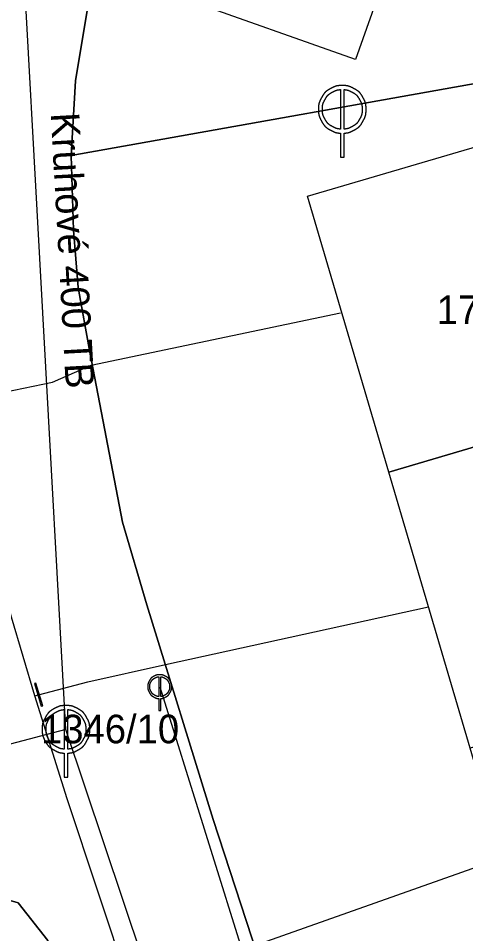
# Model space of a CAD drawing. Extents: x -562248 to -562040, y -1079385 to -1079027.
# Drawn here: x -562125.69 to -562102.21, y -1079149.79 to -1079101.77 of the extents above; entities that cross this region are included whole.
import ezdxf

# ---------------------------------------------------------------- set-up
doc = ezdxf.new("R2010")
doc.units = 0
for name, color, linetype in [('Armatura vodovodní', 7, 'Continuous'), ('Default', 7, 'Continuous'), ('Kanalizační stoka', 7, 'Continuous'), ('Kanalizační šachta', 7, 'Continuous'), ('Parcela-polygon', 7, 'Continuous'), ('Parcela-text', 7, 'Continuous'), ('Popis kmenové stoky', 7, 'Continuous'), ('Vodovodní přípojka', 7, 'Continuous'), ('Vodovodní řad', 7, 'Continuous')]:
    doc.layers.add(name, color=color, linetype=linetype)

msp = doc.modelspace()

# ---------------------------------------------------------------- linework, layer by layer
at = {"layer": 'Armatura vodovodní'}
msp.add_lwpolyline([(-562124.488, -1079137.861), (-562124.413, -1079137.839), (-562124.774, -1079136.642), (-562124.849, -1079136.665)], close=True, dxfattribs=at)
at = {"layer": 'Default'}
for points in [[(-562109.303, -1079105.459), (-562109.502, -1079105.567), (-562109.657, -1079105.721), (-562109.769, -1079105.921)], [(-562108.688, -1079105.298), (-562108.899, -1079105.298), (-562109.105, -1079105.352), (-562109.303, -1079105.459)], [(-562108.074, -1079105.459), (-562108.273, -1079105.352), (-562108.478, -1079105.298), (-562108.688, -1079105.298)], [(-562107.606, -1079105.921), (-562107.719, -1079105.721), (-562107.874, -1079105.567), (-562108.074, -1079105.459)], [(-562109.769, -1079105.921), (-562109.882, -1079106.121), (-562109.938, -1079106.33), (-562109.938, -1079106.548)], [(-562109.591, -1079106.027), (-562109.498, -1079105.86), (-562109.369, -1079105.732), (-562109.203, -1079105.642)], [(-562109.203, -1079105.642), (-562109.06, -1079105.566), (-562108.922, -1079105.522), (-562108.79, -1079105.511)], [(-562108.585, -1079105.511), (-562108.453, -1079105.522), (-562108.317, -1079105.566), (-562108.175, -1079105.642)], [(-562108.175, -1079105.642), (-562108.009, -1079105.732), (-562107.879, -1079105.86), (-562107.786, -1079106.027)], [(-562107.438, -1079106.548), (-562107.438, -1079106.33), (-562107.494, -1079106.121), (-562107.606, -1079105.921)], [(-562109.73, -1079106.548), (-562109.73, -1079106.368), (-562109.684, -1079106.194), (-562109.591, -1079106.027)], [(-562107.786, -1079106.027), (-562107.692, -1079106.194), (-562107.645, -1079106.368), (-562107.645, -1079106.548)], [(-562109.938, -1079106.548), (-562109.938, -1079106.765), (-562109.883, -1079106.972), (-562109.773, -1079107.171)], [(-562109.594, -1079107.066), (-562109.685, -1079106.901), (-562109.73, -1079106.729), (-562109.73, -1079106.548)], [(-562107.645, -1079106.548), (-562107.645, -1079106.729), (-562107.691, -1079106.901), (-562107.782, -1079107.066)], [(-562107.603, -1079107.171), (-562107.493, -1079106.972), (-562107.438, -1079106.765), (-562107.438, -1079106.548)], [(-562109.773, -1079107.171), (-562109.663, -1079107.369), (-562109.509, -1079107.523), (-562109.31, -1079107.632)], [(-562109.208, -1079107.449), (-562109.374, -1079107.358), (-562109.502, -1079107.23), (-562109.594, -1079107.066)], [(-562107.782, -1079107.066), (-562107.873, -1079107.23), (-562108.001, -1079107.358), (-562108.165, -1079107.449)], [(-562108.065, -1079107.632), (-562107.867, -1079107.523), (-562107.712, -1079107.369), (-562107.603, -1079107.171)], [(-562109.31, -1079107.632), (-562109.136, -1079107.73), (-562108.963, -1079107.784), (-562108.79, -1079107.796)], [(-562108.79, -1079107.583), (-562108.927, -1079107.574), (-562109.066, -1079107.529), (-562109.208, -1079107.449)], [(-562108.165, -1079107.449), (-562108.309, -1079107.529), (-562108.449, -1079107.574), (-562108.585, -1079107.583)], [(-562108.585, -1079107.796), (-562108.413, -1079107.784), (-562108.239, -1079107.73), (-562108.065, -1079107.632)], [(-562118.27, -1079136.205), (-562118.376, -1079136.205), (-562118.478, -1079136.232), (-562118.578, -1079136.286)], [(-562117.962, -1079136.286), (-562118.062, -1079136.232), (-562118.164, -1079136.205), (-562118.27, -1079136.205)], [(-562118.811, -1079136.516), (-562118.867, -1079136.616), (-562118.895, -1079136.721), (-562118.895, -1079136.83)], [(-562118.578, -1079136.286), (-562118.677, -1079136.339), (-562118.755, -1079136.416), (-562118.811, -1079136.516)], [(-562118.79, -1079136.83), (-562118.79, -1079136.739), (-562118.767, -1079136.652), (-562118.72, -1079136.569)], [(-562118.72, -1079136.569), (-562118.674, -1079136.486), (-562118.609, -1079136.421), (-562118.526, -1079136.376)], [(-562118.526, -1079136.376), (-562118.455, -1079136.338), (-562118.386, -1079136.316), (-562118.321, -1079136.31)], [(-562118.219, -1079136.31), (-562118.152, -1079136.316), (-562118.084, -1079136.338), (-562118.014, -1079136.376)], [(-562118.014, -1079136.376), (-562117.931, -1079136.421), (-562117.866, -1079136.486), (-562117.818, -1079136.569)], [(-562117.729, -1079136.516), (-562117.785, -1079136.416), (-562117.863, -1079136.339), (-562117.962, -1079136.286)], [(-562117.818, -1079136.569), (-562117.771, -1079136.652), (-562117.748, -1079136.739), (-562117.748, -1079136.83)], [(-562117.645, -1079136.83), (-562117.645, -1079136.721), (-562117.673, -1079136.616), (-562117.729, -1079136.516)], [(-562118.895, -1079136.83), (-562118.895, -1079136.937), (-562118.867, -1079137.041), (-562118.812, -1079137.14)], [(-562118.812, -1079137.14), (-562118.757, -1079137.239), (-562118.679, -1079137.317), (-562118.58, -1079137.372)], [(-562118.722, -1079137.088), (-562118.767, -1079137.005), (-562118.79, -1079136.92), (-562118.79, -1079136.83)], [(-562118.529, -1079137.279), (-562118.612, -1079137.234), (-562118.676, -1079137.17), (-562118.722, -1079137.088)], [(-562117.816, -1079137.088), (-562117.861, -1079137.17), (-562117.926, -1079137.234), (-562118.009, -1079137.279)], [(-562117.958, -1079137.372), (-562117.858, -1079137.317), (-562117.781, -1079137.239), (-562117.727, -1079137.14)], [(-562117.748, -1079136.83), (-562117.748, -1079136.92), (-562117.77, -1079137.005), (-562117.816, -1079137.088)], [(-562117.727, -1079137.14), (-562117.672, -1079137.041), (-562117.645, -1079136.937), (-562117.645, -1079136.83)], [(-562118.58, -1079137.372), (-562118.494, -1079137.421), (-562118.408, -1079137.448), (-562118.321, -1079137.453)], [(-562118.321, -1079137.348), (-562118.39, -1079137.343), (-562118.459, -1079137.32), (-562118.529, -1079137.279)], [(-562118.009, -1079137.279), (-562118.08, -1079137.32), (-562118.15, -1079137.343), (-562118.219, -1079137.348)], [(-562118.219, -1079137.453), (-562118.132, -1079137.448), (-562118.045, -1079137.421), (-562117.958, -1079137.372)], [(-562123.805, -1079137.981), (-562124.004, -1079138.089), (-562124.159, -1079138.242), (-562124.272, -1079138.443)], [(-562123.19, -1079137.82), (-562123.402, -1079137.82), (-562123.607, -1079137.874), (-562123.805, -1079137.981)], [(-562123.705, -1079138.164), (-562123.562, -1079138.088), (-562123.424, -1079138.044), (-562123.293, -1079138.032)], [(-562122.576, -1079137.981), (-562122.775, -1079137.874), (-562122.98, -1079137.82), (-562123.19, -1079137.82)], [(-562123.087, -1079138.032), (-562122.956, -1079138.044), (-562122.819, -1079138.088), (-562122.677, -1079138.164)], [(-562122.108, -1079138.443), (-562122.221, -1079138.242), (-562122.377, -1079138.089), (-562122.576, -1079137.981)], [(-562124.272, -1079138.443), (-562124.384, -1079138.643), (-562124.44, -1079138.852), (-562124.44, -1079139.07)], [(-562124.232, -1079139.07), (-562124.232, -1079138.889), (-562124.186, -1079138.716), (-562124.093, -1079138.549)], [(-562124.093, -1079138.549), (-562124.001, -1079138.382), (-562123.871, -1079138.254), (-562123.705, -1079138.164)], [(-562122.677, -1079138.164), (-562122.511, -1079138.254), (-562122.381, -1079138.382), (-562122.288, -1079138.549)], [(-562122.288, -1079138.549), (-562122.194, -1079138.716), (-562122.148, -1079138.889), (-562122.148, -1079139.07)], [(-562121.94, -1079139.07), (-562121.94, -1079138.852), (-562121.996, -1079138.643), (-562122.108, -1079138.443)], [(-562124.44, -1079139.07), (-562124.44, -1079139.286), (-562124.385, -1079139.494), (-562124.275, -1079139.693)], [(-562124.096, -1079139.588), (-562124.187, -1079139.423), (-562124.232, -1079139.251), (-562124.232, -1079139.07)], [(-562122.148, -1079139.07), (-562122.148, -1079139.251), (-562122.193, -1079139.423), (-562122.284, -1079139.588)], [(-562122.105, -1079139.693), (-562121.995, -1079139.494), (-562121.94, -1079139.286), (-562121.94, -1079139.07)], [(-562123.71, -1079139.971), (-562123.876, -1079139.88), (-562124.005, -1079139.752), (-562124.096, -1079139.588)], [(-562122.284, -1079139.588), (-562122.375, -1079139.752), (-562122.503, -1079139.88), (-562122.668, -1079139.971)], [(-562124.275, -1079139.693), (-562124.165, -1079139.891), (-562124.011, -1079140.045), (-562123.813, -1079140.154)], [(-562123.293, -1079140.105), (-562123.429, -1079140.095), (-562123.568, -1079140.051), (-562123.71, -1079139.971)], [(-562122.668, -1079139.971), (-562122.811, -1079140.051), (-562122.951, -1079140.095), (-562123.087, -1079140.105)], [(-562122.567, -1079140.154), (-562122.369, -1079140.045), (-562122.215, -1079139.891), (-562122.105, -1079139.693)], [(-562123.813, -1079140.154), (-562123.638, -1079140.252), (-562123.465, -1079140.306), (-562123.293, -1079140.318)], [(-562123.087, -1079140.318), (-562122.915, -1079140.306), (-562122.742, -1079140.252), (-562122.567, -1079140.154)]]:
    msp.add_open_spline(points, degree=2, dxfattribs=at)
at = {"layer": 'Kanalizační stoka'}
for points in [[(-562123.19, -1079139.07), (-562125.61, -1079095.35)], [(-562118.27, -1079136.83), (-562108.95, -1079166.63)], [(-562123.19, -1079139.07), (-562151.509, -1079146.524)], [(-562098.95, -1079211.35), (-562123.19, -1079139.07)]]:
    msp.add_lwpolyline(points, dxfattribs=at)
at = {"layer": 'Kanalizační šachta'}
for points in [[(-562108.79, -1079105.511), (-562108.79, -1079107.583)], [(-562108.585, -1079107.583), (-562108.585, -1079105.511)], [(-562108.79, -1079109.048), (-562108.585, -1079109.048), (-562108.585, -1079107.796)], [(-562108.79, -1079107.796), (-562108.79, -1079109.048)], [(-562118.321, -1079136.31), (-562118.321, -1079137.348)], [(-562118.219, -1079137.348), (-562118.219, -1079136.31)], [(-562118.321, -1079138.08), (-562118.219, -1079138.08), (-562118.219, -1079137.453)], [(-562118.321, -1079137.453), (-562118.321, -1079138.08)], [(-562123.293, -1079138.032), (-562123.293, -1079140.105)], [(-562123.087, -1079140.105), (-562123.087, -1079138.032)], [(-562123.293, -1079141.57), (-562123.087, -1079141.57), (-562123.087, -1079140.318)], [(-562123.293, -1079140.318), (-562123.293, -1079141.57)]]:
    msp.add_lwpolyline(points, dxfattribs=at)
at = {"layer": 'Parcela-polygon'}
for points in [[(-562089.427, -1079062.836), (-562106.84, -1079056.62), (-562119.65, -1079091.82), (-562121.03, -1079096.76), (-562122.05, -1079101.16), (-562122.69, -1079105.05), (-562122.92, -1079108.96), (-562097.98, -1079104.526)], [(-562117.01, -1079100.74), (-562111.46, -1079085.11), (-562105.93, -1079069.43), (-562096.89, -1079072.69), (-562102.44, -1079088.31), (-562107.99, -1079103.94), (-562117.01, -1079100.74)], [(-562074.7, -1079253.09), (-562081.96, -1079237.32), (-562088.81, -1079221.44), (-562094.66, -1079207.06), (-562098.96, -1079196.12), (-562103.67, -1079183.92), (-562101.64, -1079183.14), (-562108.26, -1079165.24), (-562109.03, -1079162.72), (-562110.57, -1079158.43), (-562113.13, -1079150.92), (-562115.47, -1079143.79), (-562118.94, -1079132.53), (-562120.22, -1079128.2), (-562121.94, -1079119.29), (-562122.55, -1079115.89), (-562122.79, -1079112.89), (-562122.92, -1079108.96), (-562122.69, -1079105.05), (-562122.05, -1079101.16)], [(-562097.98, -1079104.526), (-562122.92, -1079108.96), (-562122.79, -1079112.89), (-562122.55, -1079115.89), (-562121.94, -1079119.29), (-562120.22, -1079128.2), (-562118.94, -1079132.53), (-562115.47, -1079143.79), (-562113.13, -1079150.92), (-562110.57, -1079158.43), (-562109.03, -1079162.72), (-562081.378, -1079153.144)], [(-562101.27, -1079108.39), (-562097, -1079122.85), (-562092.73, -1079137.34), (-562088.46, -1079151.82), (-562097.7, -1079154.55), (-562101.98, -1079140.06), (-562106.25, -1079125.58), (-562110.52, -1079111.1), (-562101.27, -1079108.39)], [(-562130.204, -1079213.482), (-562129.52, -1079213.24), (-562126.56, -1079212.06), (-562110.18, -1079204.89), (-562109.412, -1079204.67), (-562108.694, -1079204.319), (-562108.049, -1079203.848), (-562107.496, -1079203.271), (-562107.054, -1079202.606), (-562106.734, -1079201.874), (-562106.547, -1079201.097), (-562106.5, -1079200.3), (-562107.01, -1079197.84), (-562112.9, -1079182.58), (-562117.83, -1079168.5), (-562124.14, -1079150.14), (-562125.7, -1079148.16), (-562127.71, -1079147.6), (-562130.14, -1079147.9), (-562151.942, -1079151.733)], [(-562151.942, -1079151.733), (-562130.14, -1079147.9), (-562127.71, -1079147.6), (-562125.7, -1079148.16), (-562124.14, -1079150.14), (-562117.83, -1079168.5), (-562112.9, -1079182.58), (-562107.01, -1079197.84), (-562106.5, -1079200.3), (-562100.28, -1079214.7), (-562095.19, -1079227.16), (-562092.25, -1079234.14), (-562087.93, -1079243.96)]]:
    msp.add_lwpolyline(points, dxfattribs=at)
for points in [[(-562111.46, -1079085.11), (-562102.44, -1079088.31), (-562107.99, -1079103.94), (-562117.01, -1079100.74)], [(-562110.52, -1079111.1), (-562101.27, -1079108.39), (-562097, -1079122.85), (-562106.25, -1079125.58)], [(-562097, -1079122.85), (-562092.73, -1079137.34), (-562101.98, -1079140.06), (-562106.25, -1079125.58)]]:
    msp.add_lwpolyline(points, close=True, dxfattribs=at)
at = {"layer": 'Vodovodní přípojka'}
for points in [[(-562128.484, -1079121.808), (-562123.89, -1079120.86), (-562121.868, -1079119.966), (-562108.775, -1079117.222)], [(-562124.818, -1079137.317), (-562124.633, -1079137.252), (-562122.045, -1079136.57), (-562117.961, -1079135.673), (-562104.167, -1079132.643)], [(-562119.874, -1079152.505), (-562119.666, -1079152.467), (-562119.205, -1079152.27), (-562115.221, -1079151.096), (-562100.139, -1079145.758)]]:
    msp.add_lwpolyline(points, dxfattribs=at)
at = {"layer": 'Vodovodní řad'}
msp.add_lwpolyline([(-562104.508, -1079195.68), (-562105.675, -1079193.599), (-562106.045, -1079192.495), (-562108.292, -1079185.845), (-562110.54, -1079179.194), (-562111.609, -1079176.901), (-562113.474, -1079171.283), (-562115.559, -1079165.192), (-562118.308, -1079157.281), (-562119.874, -1079152.505), (-562123.128, -1079142.718), (-562124.818, -1079137.317), (-562126.048, -1079133.176), (-562126.972, -1079129.683), (-562127.886, -1079125.317), (-562128.484, -1079121.808), (-562129.183, -1079117.074), (-562129.389, -1079112.24), (-562129.474, -1079106.997), (-562129.319, -1079103.524), (-562128.819, -1079100.288), (-562128.175, -1079096.35), (-562128.115, -1079096.032)], dxfattribs=at)

# ---------------------------------------------------------------- texts
at = {"layer": 'Parcela-text'}
for s, p in [('1717/1', (-562103.73, -1079117.81)), ('1346/10', (-562124.5, -1079139.8))]:
    msp.add_text(s, height=1.5, dxfattribs=at).set_placement(p)
at = {"layer": 'Popis kmenové stoky'}
msp.add_text('Kruhové 400 TB', height=1.5, rotation=273.1682, dxfattribs=at).set_placement((-562123.993, -1079106.75))

doc.saveas('drawing.dxf')
